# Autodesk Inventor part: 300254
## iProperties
Created: 2007-11
Part Number: 300254
Document SubType Name: Modeling
Designer: TH
Density: 7.85 g/cm^3
Mass: 336.369 g
Surface Area: 156.51 cm^2
Volume: 42.8495 cm^3
Material: Steel
Description: BACK PIVOT PLATE
Component Category: Back Component
Author: TH
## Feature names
1. Extrusion1
2. Extrusion2
3. Chamfer1
4. Mirror1
5. Extrusion3
6. Chamfer2
7. Mirror2
8. Extrusion4
9. Revolution1
10. Revolution2
11. Circular Pattern2
12. Extrusion6
13. Fillet2
14. Circular Pattern3
15. Fillet3
